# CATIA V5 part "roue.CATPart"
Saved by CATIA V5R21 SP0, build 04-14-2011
Part number: roue
Revision: A
Nomenclature: 3
Material "Aluminium": density 2710 kg/m3, Young's modulus 7e+10 Pa, Poisson ratio 0.346, thermal expansion 2.36e-05 1/K
Bounding box of the stored display mesh (mm): x -36.5 to 20, y -31 to 31, z -31 to 31
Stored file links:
  C:\Users\Utilisateur\Desktop\Fichiers à télécharger dans l'ouvrage\Exercice 9 Pompe de ventilation.CATDrawing (corrigé)\roue.CATPart
  C:\Program Files\Dassault Systemes\B21\win_b64\startup\materials\French\Catalog.CATMaterial
  C:\Users\Utilisateur\Desktop\Fichiers à télécharger dans l'ouvrage\Exercice 9 Pompe de ventilation.CATDrawing (corrigé)\CATIA_EnvironmentMap_Satin_512x512.jpg
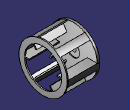
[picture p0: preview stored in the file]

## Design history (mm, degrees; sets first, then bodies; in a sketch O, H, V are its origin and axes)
Body1 (main body), material "Aluminium"
  Sketch1 on yz-plane, origin (0, 0, 0), H (0, 1, 0), V (0, 0, 1)
    arc A1 centre (0, 0) radius 31 from (21.7261, 22.1128) to (14.8459, 27.2139) ccw
    arc A2 centre (0, 0) radius 29.5 from (20.6749, 21.0428) to (15.3948, 25.1645) ccw
    line L1 (9.6319, 15.1829) -> (15.3948, 25.1645)
    line L2 (8.3328, 15.9329) -> (14.8459, 27.2139)
    construction line L3 (0, 0) -> (-1.299, 0.75)
    line L4 (20.6749, 21.0428) -> (21.7261, 22.1128)
    arc A3 centre (0, 0) radius 17.9804 from (9.6319, 15.1829) to (8.3328, 15.9329) ccw
    angle L1 H = 60
    distance L1 L2 = 1.5
    distance A1 A2 = 1.5
    radius A1 = 31
    perpendicularity: L3 L1, L3 L2
  Pad1: profile Sketch1, direction (1, 0, 0), length 20, mirrored extent
  Sketch2 on start face of Pad1, origin (-20, 0, 0), H (0, -1, 0), V (0, 0, 1)
    reference projected arc E1 centre (0, 0) radius 31 from (-14.8459, 27.2139) to (-21.7261, 22.1128) ccw from edge [start face of Pad1 | face of Pad1 from Sketch1.A1]
    circle A1 centre (0, 0) radius 31
    point P3 (-17.8616, 25.337)
    circle A2 centre (0, 0) radius 2.5
    circle A3 centre (0, 0) radius 8
    radius A2 = 2.5
    radius A3 = 8
    coincidence: A1 P3, P3 E1
  Sketch3 on end face of Pad1, origin (20, 0, 0), H (0, 1, 0), V (0, 0, 1)
    circle A1 centre (0, 0) radius 24
    circle A2 centre (0, 0) radius 31
    radius A1 = 24
    radius A2 = 31
  Pad2: profile Sketch3, direction (-1, 0, 0), length 1.5
  MultiPad1: profile Sketch2, domains (length 16.5; length 0; length 2 / length 1)
  Sketch4 on face of MultiPad1, origin (-36.5, 0, 0), H (0, -1, 0), V (0, 0, 1)
    circle A1 centre (0, 0) radius 4.5
  Pocket1: profile Sketch4, direction (1, 0, 0), length 12
  CircPattern1: of Pad1, instances 6, angular step 60, axis from end face of Pad2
